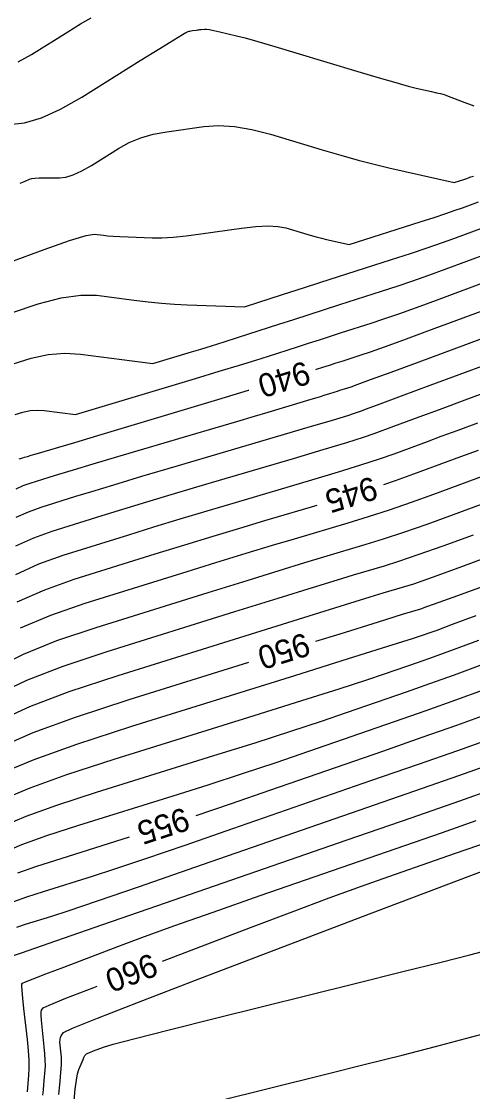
# Model space of a CAD drawing. Extents: x 2175772 to 2185556, y 721391 to 722853.
# Drawn here: x 2178748.5 to 2178802.7, y 721969.8 to 722098.3 of the extents above; entities that cross this region are included whole.
import ezdxf

# ---------------------------------------------------------------- set-up
doc = ezdxf.new("R2010")
doc.units = 0
doc.layers.add('DT_X_Contour_Major', color=7, linetype='Continuous')
doc.layers.add('DT_X_Contour_Minor', color=7, linetype='Continuous')

msp = doc.modelspace()

# ---------------------------------------------------------------- linework, layer by layer
at = {"layer": 'DT_X_Contour_Major'}
for points in [[(2178748.36, 722078.91), (2178748.98, 722079.17), (2178749.5, 722079.39), (2178749.76, 722079.46), (2178750.14, 722079.51), (2178750.64, 722079.54), (2178751.27, 722079.55), (2178753.1, 722079.54), (2178753.85, 722079.63), (2178754.74, 722079.91), (2178755.76, 722080.39), (2178756.92, 722081.05), (2178760.18, 722083.09), (2178761.46, 722083.78), (2178762.85, 722084.35), (2178764.36, 722084.78), (2178765.98, 722085.08), (2178770.44, 722085.71), (2178772.19, 722085.83), (2178774.11, 722085.72), (2178776.19, 722085.37), (2178778.43, 722084.79), (2178784.62, 722082.93), (2178786.86, 722082.27), (2178788.94, 722081.69), (2178790.87, 722081.19), (2178792.63, 722080.77), (2178800.47, 722079), (2178801.74, 722079.41), (2178801.99, 722079.49), (2178802.19, 722079.56), (2178802.36, 722079.62), (2178802.49, 722079.66), (2178802.78, 722079.77)], [(2178783.86, 722056.55), (2178783.93, 722056.57), (2178784.73, 722056.82), (2178785.53, 722057.08), (2178786.33, 722057.34), (2178787.15, 722057.6), (2178789.32, 722058.3), (2178790.43, 722058.67), (2178792.13, 722059.28), (2178794.43, 722060.11), (2178797.31, 722061.18), (2178805.8, 722064.32)], [(2178748.25, 722045.8), (2178748.69, 722045.94), (2178748.91, 722046.01), (2178749.25, 722046.11), (2178749.71, 722046.24), (2178750.28, 722046.41), (2178751.95, 722046.91), (2178753.01, 722047.22), (2178754.92, 722047.79), (2178757.69, 722048.62), (2178761.31, 722049.71), (2178772.12, 722052.95), (2178775.77, 722054.05), (2178775.84, 722054.07)], [(2178792.05, 722042.75), (2178793.43, 722043.21), (2178795.64, 722044), (2178801.27, 722046.08), (2178803.41, 722046.87)], [(2178748.03, 722028.64), (2178751.32, 722030.11), (2178754.85, 722031.36), (2178764.59, 722034.4), (2178768.16, 722035.5), (2178771.54, 722036.54), (2178774.74, 722037.51), (2178777.76, 722038.41), (2178784.03, 722040.26)], [(2178769.49, 722003.01), (2178773.63, 722004.41), (2178778.45, 722006.06), (2178791.91, 722010.73), (2178796.65, 722012.39), (2178800.78, 722013.85), (2178804.3, 722015.12), (2178807.21, 722016.19), (2178814.14, 722018.8), (2178816.89, 722019.85), (2178819.96, 722021.01), (2178823.34, 722022.31), (2178827.03, 722023.73), (2178837.28, 722027.69), (2178841.1, 722029.15), (2178844.85, 722030.58), (2178848.54, 722031.97), (2178852.17, 722033.31), (2178861.75, 722036.86), (2178863.36, 722037.45)], [(2178783.86, 722023.91), (2178786.79, 722024.82), (2178791.39, 722026.26), (2178794.29, 722027.16), (2178795.5, 722027.53), (2178796.47, 722027.82), (2178797.21, 722028.07), (2178798.69, 722028.6), (2178800.92, 722029.41), (2178803.89, 722030.51)], [(2178746.2, 722011.34), (2178749.92, 722012.95), (2178755.01, 722014.81), (2178761.46, 722016.91), (2178775.84, 722021.41)], [(2178765.46, 721985.51), (2178776.02, 721989.54), (2178781.04, 721991.45), (2178785.48, 721993.1), (2178789.35, 721994.51), (2178792.64, 721995.68), (2178800.65, 721998.46), (2178803.33, 721999.39), (2178805.37, 722000.1), (2178806.76, 722000.59), (2178807.5, 722000.86), (2178808.62, 722001.28), (2178809.92, 722001.78), (2178812.98, 722002.95), (2178817.79, 722004.81), (2178824.36, 722007.34), (2178844.22, 722015), (2178850.81, 722017.54), (2178855.69, 722019.42), (2178858.84, 722020.63), (2178859.05, 722020.71)], [(2178748.11, 721996.1), (2178750.37, 721996.91), (2178753.28, 721997.85), (2178761.5, 722000.42)], [(2178751.11, 721969.41), (2178751.17, 721970.07), (2178751.22, 721970.66), (2178751.26, 721971.18), (2178751.38, 721972.47), (2178751.4, 721973), (2178751.39, 721973.64), (2178751.34, 721974.39), (2178751.26, 721975.24), (2178751, 721977.64), (2178750.92, 721978.44), (2178750.88, 721979.04), (2178750.89, 721979.44), (2178750.94, 721979.64), (2178751.12, 721979.9), (2178751.84, 721980.24), (2178753.87, 721981.06), (2178757.22, 721982.36), (2178757.61, 721982.51)]]:
    msp.add_lwpolyline(points, dxfattribs=at)
at = {"layer": 'DT_X_Contour_Minor'}
for points in [[(2178748.14, 722093.5), (2178749.74, 722094.38), (2178754.09, 722097.1), (2178755.61, 722098.03), (2178756.91, 722098.78)], [(2178747.05, 722085.96), (2178748.88, 722086.16), (2178750.94, 722086.77), (2178753.23, 722087.79), (2178755.76, 722089.23), (2178762.8, 722093.63), (2178765.13, 722095.07), (2178766.81, 722096.12), (2178767.86, 722096.76), (2178768.28, 722097), (2178768.53, 722097.11), (2178768.63, 722097.15), (2178768.75, 722097.18), (2178768.89, 722097.21), (2178769.05, 722097.24), (2178769.49, 722097.3), (2178769.65, 722097.32), (2178769.81, 722097.34), (2178769.96, 722097.36), (2178770.11, 722097.37), (2178770.5, 722097.41), (2178770.73, 722097.41), (2178771.11, 722097.35), (2178771.64, 722097.24), (2178772.33, 722097.09), (2178774.36, 722096.61), (2178775.38, 722096.35), (2178776.91, 722095.92), (2178778.94, 722095.33), (2178781.48, 722094.57), (2178788.93, 722092.33), (2178791.46, 722091.58), (2178793.47, 722090.99), (2178794.95, 722090.58), (2178795.91, 722090.34), (2178797.75, 722089.92), (2178798.36, 722089.78), (2178798.83, 722089.67), (2178799.13, 722089.6), (2178799.29, 722089.55), (2178799.49, 722089.47), (2178799.76, 722089.37), (2178800.41, 722089.13), (2178801.44, 722088.74), (2178802.84, 722088.21)], [(2178747.12, 722069.44), (2178751.24, 722070.95), (2178754.3, 722072.02), (2178756.3, 722072.63), (2178757.25, 722072.8), (2178758.37, 722072.66), (2178758.87, 722072.61), (2178759.54, 722072.56), (2178760.36, 722072.51), (2178761.36, 722072.47), (2178764.22, 722072.37), (2178765.39, 722072.37), (2178766.75, 722072.45), (2178768.31, 722072.6), (2178770.05, 722072.82), (2178774.96, 722073.51), (2178776.67, 722073.71), (2178778.13, 722073.78), (2178779.32, 722073.72), (2178780.25, 722073.55), (2178782.4, 722072.9), (2178783.18, 722072.67), (2178783.9, 722072.47), (2178784.56, 722072.3), (2178785.17, 722072.15), (2178787.89, 722071.54), (2178796.38, 722074.26), (2178798.06, 722074.81), (2178799.46, 722075.27), (2178800.6, 722075.66), (2178801.46, 722075.97), (2178803.38, 722076.68)], [(2178747.33, 722063.33), (2178750.53, 722064.42), (2178753.3, 722065.14), (2178755.64, 722065.48), (2178757.55, 722065.45), (2178762.07, 722064.86), (2178763.74, 722064.67), (2178765.35, 722064.51), (2178766.91, 722064.39), (2178768.42, 722064.32), (2178775.31, 722064.08), (2178779.86, 722065.54), (2178782.51, 722066.39), (2178784.37, 722066.99), (2178786.59, 722067.7), (2178792.96, 722069.74), (2178795.22, 722070.48), (2178797.22, 722071.14), (2178798.95, 722071.74), (2178800.42, 722072.27), (2178803.99, 722073.59)], [(2178747.55, 722057.23), (2178749.69, 722057.92), (2178751.74, 722058.33), (2178753.72, 722058.49), (2178755.62, 722058.38), (2178764.3, 722057.26), (2178768.95, 722058.65), (2178770.05, 722058.99), (2178771.36, 722059.39), (2178772.86, 722059.87), (2178774.58, 722060.42), (2178779.41, 722061.97), (2178781.23, 722062.55), (2178784.91, 722063.73), (2178786.77, 722064.33), (2178791.75, 722065.93), (2178793.63, 722066.54), (2178795.52, 722067.19), (2178797.44, 722067.86), (2178799.38, 722068.57), (2178804.59, 722070.5)], [(2178747.77, 722051.13), (2178748.69, 722051.43), (2178749.58, 722051.61), (2178750.43, 722051.68), (2178751.25, 722051.63), (2178755, 722051.14), (2178769.41, 722055.47), (2178772.28, 722056.33), (2178774.7, 722057.06), (2178776.67, 722057.67), (2178778.2, 722058.15), (2178781.67, 722059.27), (2178782.98, 722059.69), (2178784.3, 722060.11), (2178785.62, 722060.54), (2178786.96, 722060.97), (2178790.53, 722062.11), (2178792.03, 722062.61), (2178793.83, 722063.23), (2178795.94, 722063.99), (2178798.35, 722064.88), (2178805.19, 722067.41)], [(2178747.91, 722042.23), (2178748.72, 722042.61), (2178749.57, 722042.91), (2178751.87, 722043.63), (2178753.03, 722043.99), (2178754.79, 722044.51), (2178757.15, 722045.22), (2178760.1, 722046.09), (2178768.77, 722048.65), (2178771.8, 722049.54), (2178774.37, 722050.3), (2178776.49, 722050.93), (2178778.16, 722051.43), (2178782, 722052.58), (2178783.29, 722052.97), (2178784.3, 722053.28), (2178785.01, 722053.5), (2178785.44, 722053.63), (2178786.19, 722053.87), (2178786.47, 722053.96), (2178786.76, 722054.05), (2178787.04, 722054.14), (2178787.33, 722054.24), (2178788.11, 722054.48), (2178788.83, 722054.74), (2178790.44, 722055.33), (2178792.92, 722056.24), (2178796.28, 722057.48), (2178806.4, 722061.23)], [(2178747.89, 722038.8), (2178749.36, 722039.47), (2178750.89, 722040.02), (2178755.05, 722041.32), (2178756.98, 722041.91), (2178759.63, 722042.71), (2178763, 722043.72), (2178767.11, 722044.93), (2178779.02, 722048.45), (2178782.96, 722049.62), (2178785.86, 722050.48), (2178787.71, 722051.04), (2178788.5, 722051.29), (2178789.24, 722051.56), (2178789.97, 722051.83), (2178791.6, 722052.44), (2178794.15, 722053.38), (2178797.6, 722054.66), (2178808.02, 722058.52)], [(2178747.87, 722035.37), (2178750, 722036.34), (2178752.21, 722037.13), (2178758.23, 722039.01), (2178760.7, 722039.78), (2178763.6, 722040.66), (2178766.92, 722041.65), (2178770.66, 722042.76), (2178781.2, 722045.87), (2178784.77, 722046.93), (2178787.58, 722047.79), (2178789.61, 722048.43), (2178790.88, 722048.86), (2178793.25, 722049.73), (2178796.27, 722050.86), (2178798.73, 722051.76), (2178801.81, 722052.91), (2178810.87, 722056.26)], [(2178747.85, 722031.93), (2178750.63, 722033.21), (2178753.53, 722034.24), (2178761.41, 722036.71), (2178764.43, 722037.64), (2178767.57, 722038.6), (2178770.83, 722039.58), (2178774.21, 722040.58), (2178783.38, 722043.29), (2178786.58, 722044.25), (2178789.29, 722045.09), (2178791.52, 722045.82), (2178793.26, 722046.43), (2178797.26, 722047.91), (2178798.93, 722048.53), (2178800.95, 722049.27), (2178803.31, 722050.15)], [(2178748.41, 722025.51), (2178752.06, 722027.05), (2178756.17, 722028.47), (2178767.77, 722032.09), (2178771.88, 722033.37), (2178775.51, 722034.48), (2178778.65, 722035.44), (2178781.3, 722036.23), (2178787.74, 722038.13), (2178790.2, 722038.88), (2178792.73, 722039.71), (2178795.34, 722040.6), (2178798.02, 722041.57), (2178805.28, 722044.25)], [(2178745.46, 722020.71), (2178748.78, 722022.37), (2178752.79, 722023.99), (2178757.5, 722025.58), (2178770.95, 722029.78), (2178775.61, 722031.23), (2178779.48, 722032.43), (2178782.56, 722033.37), (2178784.85, 722034.06), (2178789.93, 722035.56), (2178792.01, 722036.2), (2178794.45, 722037.01), (2178797.24, 722037.99), (2178800.4, 722039.14), (2178809.29, 722042.43)], [(2178745.71, 722017.59), (2178749.16, 722019.23), (2178753.53, 722020.93), (2178758.82, 722022.69), (2178774.14, 722027.47), (2178779.34, 722029.1), (2178783.45, 722030.37), (2178786.47, 722031.3), (2178788.4, 722031.88), (2178792.11, 722032.98), (2178793.82, 722033.52), (2178796.16, 722034.32), (2178799.15, 722035.39), (2178802.78, 722036.71)], [(2178745.95, 722014.46), (2178749.54, 722016.09), (2178754.27, 722017.87), (2178760.14, 722019.8), (2178777.32, 722025.17), (2178783.06, 722026.96), (2178787.42, 722028.31), (2178790.38, 722029.23), (2178791.95, 722029.71), (2178794.29, 722030.4), (2178795.62, 722030.83), (2178797.88, 722031.63), (2178801.06, 722032.78), (2178805.15, 722034.28)], [(2178746.38, 722008.19), (2178750.04, 722009.73), (2178755.18, 722011.57), (2178761.78, 722013.71), (2178781.33, 722019.82), (2178787.79, 722021.84), (2178792.5, 722023.31), (2178795.47, 722024.25), (2178796.68, 722024.64), (2178797.6, 722024.95), (2178798.44, 722025.26), (2178800.28, 722025.95), (2178803.13, 722027.02)], [(2178746.41, 722005), (2178749.56, 722006.32), (2178753.97, 722007.91), (2178759.65, 722009.75), (2178776.47, 722015), (2178782.18, 722016.79), (2178786.69, 722018.22), (2178790.01, 722019.29), (2178792.12, 722019.99), (2178796.18, 722021.4), (2178797.99, 722022.04), (2178800.41, 722022.93), (2178803.42, 722024.04)], [(2178746.44, 722001.81), (2178749.08, 722002.92), (2178752.77, 722004.24), (2178757.53, 722005.78), (2178771.61, 722010.18), (2178776.57, 722011.74), (2178780.88, 722013.12), (2178784.55, 722014.33), (2178787.57, 722015.35), (2178794.76, 722017.84), (2178797.55, 722018.83), (2178800.53, 722019.9), (2178803.71, 722021.07)], [(2178746.47, 721998.61), (2178748.59, 721999.51), (2178751.57, 722000.58), (2178755.4, 722001.82), (2178766.75, 722005.36), (2178770.96, 722006.69), (2178775.07, 722008.03), (2178779.09, 722009.37), (2178783.01, 722010.71), (2178793.33, 722014.29), (2178797.1, 722015.61), (2178800.66, 722016.87), (2178804.01, 722018.09)], [(2178747.63, 721992.69), (2178749.17, 721993.25), (2178751.16, 721993.89), (2178757.04, 721995.73), (2178759.75, 721996.6), (2178763.46, 721997.84), (2178768.17, 721999.45), (2178773.9, 722001.42), (2178790.49, 722007.18), (2178796.21, 722009.17), (2178800.91, 722010.82), (2178804.59, 722012.14)], [(2178747.97, 721989.58), (2178749.03, 721989.93), (2178752.18, 721990.91), (2178754.14, 721991.55), (2178757.65, 721992.74), (2178762.72, 721994.49), (2178769.34, 721996.78), (2178789.07, 722003.62), (2178795.76, 722005.95), (2178801.03, 722007.8), (2178804.89, 722009.17)], [(2178747.32, 721986.09), (2178748.53, 721986.5), (2178751.84, 721987.65), (2178757.26, 721989.53), (2178764.78, 721992.14), (2178787.65, 722000.07), (2178795.31, 722002.73), (2178801.16, 722004.77), (2178805.18, 722006.19)], [(2178771.85, 721968.65), (2178785.08, 721971.94), (2178789.84, 721973.14), (2178794.22, 721974.24), (2178798.22, 721975.27), (2178801.83, 721976.21), (2178810.94, 721978.62), (2178814.37, 721979.58), (2178817.83, 721980.65), (2178821.32, 721981.84), (2178824.84, 721983.15), (2178834.27, 721986.77), (2178838.15, 721988.25), (2178842.73, 721989.96), (2178848.01, 721991.91), (2178853.99, 721994.1), (2178870.85, 722000.24), (2178876.89, 722002.41), (2178882.34, 722004.31), (2178887.23, 722005.94)], [(2178749.24, 721969.81), (2178749.41, 721971.81), (2178749.45, 721972.64), (2178749.44, 721973.64), (2178749.36, 721974.79), (2178749.24, 721976.11), (2178748.83, 721979.84), (2178748.7, 721981.07), (2178748.61, 721981.97), (2178748.58, 721982.52), (2178748.58, 721982.73), (2178748.67, 721982.85), (2178749, 721983.01), (2178749.93, 721983.39), (2178751.47, 721983.98), (2178753.6, 721984.8), (2178760.1, 721987.28), (2178763, 721988.36), (2178766.81, 721989.74), (2178771.55, 721991.41), (2178777.2, 721993.38), (2178793.5, 721999.04), (2178798.96, 722000.93), (2178803.1, 722002.38)], [(2178753.02, 721969.51), (2178753.12, 721970.68), (2178753.2, 721971.57), (2178753.26, 721972.2), (2178753.29, 721972.55), (2178753.34, 721973.13), (2178753.35, 721973.36), (2178753.34, 721973.65), (2178753.32, 721973.98), (2178753.29, 721974.36), (2178753.17, 721975.43), (2178753.14, 721975.8), (2178753.16, 721976.11), (2178753.2, 721976.36), (2178753.29, 721976.54), (2178753.57, 721976.95), (2178754.64, 721977.45), (2178757.64, 721978.67), (2178762.57, 721980.59), (2178769.44, 721983.22), (2178790.31, 721991.19), (2178797.19, 721993.81), (2178802.16, 721995.69), (2178805.23, 721996.84)], [(2178754.86, 721968.79), (2178754.99, 721970.15), (2178755.13, 721971.22), (2178755.27, 721972), (2178755.41, 721972.49), (2178755.8, 721973.41), (2178755.93, 721973.71), (2178756.03, 721973.95), (2178756.11, 721974.11), (2178756.15, 721974.19), (2178756.24, 721974.31), (2178756.32, 721974.37), (2178756.51, 721974.47), (2178756.8, 721974.59), (2178757.19, 721974.74), (2178758.37, 721975.19), (2178759.54, 721975.54), (2178762.18, 721976.23), (2178766.27, 721977.27), (2178771.83, 721978.66), (2178788.6, 721982.83), (2178794.32, 721984.25), (2178798.9, 721985.4), (2178802.34, 721986.28), (2178804.65, 721986.87)]]:
    msp.add_lwpolyline(points, dxfattribs=at)

# ---------------------------------------------------------------- texts
at = {"layer": 'DT_X_Contour_Major'}
for s, rotation, p in [('940', 197.1796, (2178782.64, 722057.61)), ('945', 197.2346, (2178790.71, 722043.76)), ('950', 197.3403, (2178782.61, 722024.99)), ('955', 197.9486, (2178768.12, 722004.02)), ('960', 200.9312, (2178764.16, 721986.52))]:
    msp.add_text(s, height=2.8, rotation=rotation, dxfattribs=at).set_placement(p)

doc.saveas('drawing.dxf')
